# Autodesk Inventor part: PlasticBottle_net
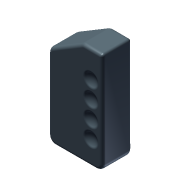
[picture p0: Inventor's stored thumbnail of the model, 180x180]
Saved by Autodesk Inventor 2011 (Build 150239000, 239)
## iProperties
Created: 2010-02
Part Number: PlasticBottle_net
Document SubType Name: Modeling
Designer: boganb
Density: 1 g/cm^3
Mass: 949.598 g
Surface Area: 626.406 cm^2
Volume: 949.598 cm^3
Author: boganb
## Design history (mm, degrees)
sketch "Sketch1"
  geometry: L1 (-53.865, -86.816)-(47.735, -86.816); L2 (47.735, -86.816)-(47.735, 103.684); L3 (47.735, 103.684)-(9.635, 103.684); L4 (9.635, 103.684)-(-53.865, 65.584); L5 (-53.865, 65.584)-(-53.865, -86.816); 1 further point
  constraints: 10 end point, 3 perpendicular, 1 horizontal
  dimensions: "d0" = 152.4 distance of L4.end L1.start; "d1" = 190.5 distance of L1.end L2.end; "d2" = 101.6 distance of L1.start L1.end; "d3" = 38.1 distance of L2.end L3.end
extrude "Extrusion1" new body sketch "Sketch1" stored distance "d4" = 55.88; taper "d5" = 0 deg
sketch "Sketch2"
  geometry: L1 (0, 0)-(38.1, 0) reference; L2 (0, 55.88)-(0, 0) reference; C1 r 12.7 at (19.05, 27.94); 3 further points
  constraints: 2 midpoint, 1 centre point, 1 horizontal alignment, 1 vertical alignment
  dimensions: "d6" = 25.4 diameter of C1
extrude "Extrusion2" join sketch "Sketch2" distance "d7" = 6.35; taper "d8" = 0 deg
sketch "Sketch3"
  geometry: C1 r 12.7 at (0, 0) reference; C2 r 11.112 at (0, 0); 1 further point
  constraints: 1 centre point
  dimensions: "d9" = 1.5875 radial gap between concentric circles of C1 C2
extrude "Extrusion3" join sketch "Sketch3" distance "d10" = 7.9375; taper "d11" = 0 deg
workplane "Work Plane1"
sketch "Sketch4"
  geometry: L1 (0, 0)-(0, 152.4) reference; L2 (0, 0)-(55.88, 0) reference; L3 (-14.288, 63.5)-(-14.287, 25.4); A1 r 19.05 centre (-14.288, 44.45) between (-14.287, 25.4) and (-14.288, 63.5); 1 further point
  constraints: 2 end point, 2 point on circle, 1 centre point, 1 midpoint, 1 perpendicular
  dimensions: "d24" = 14.2875 distance between parallel lines of L3 L1; "d25" = 19.05 radius of A1; "d32" = 44.45 distance from line of A1.centre L2
revolve "Revolution1" sketch "Sketch4" stored, may be unused: angle "d26" = 180 deg
pattern_linear "Rectangular Pattern1" dims "d29" = 31.75
fillet "Fillet1" dims "d12" = 4.7625
fillet "Fillet4" dims "d16" = 12.7
fillet "Fillet5" dims "d17" = 12.7
fillet "Fillet2" dims "d13" = 6.35
fillet "Fillet3" dims "d14" = 3.175
fillet "Fillet6" dims "d30" = 6.35
mirror "Mirror1"
fillet "Fillet7" dims "d31" = 6.35
shell "Shell1" dims "d15" = 0.635
delete_face "Delete Face1"
delete_face "Delete Face2"
feature "Stitch Surface1"
body "Solid1"
body "Srf1"
patch "Boundary Patch1" dims "d35" = 0, "d36" = 0, "d37" = 0, "d38" = 0, "d39" = 0
other parameters: "d18" = -22.225
